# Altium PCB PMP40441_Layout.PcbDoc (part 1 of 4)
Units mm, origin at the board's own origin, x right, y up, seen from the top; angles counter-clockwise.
Board outline 66.04 x 61.04 mm, 4 copper layers (Top Layer, Layer 2, Layer 3, Bottom Layer), stack 2.028 mm thick; 208 components, 122 nets, 788 pads, 545 vias.
Unrouted connection lines stored in the file: 24.
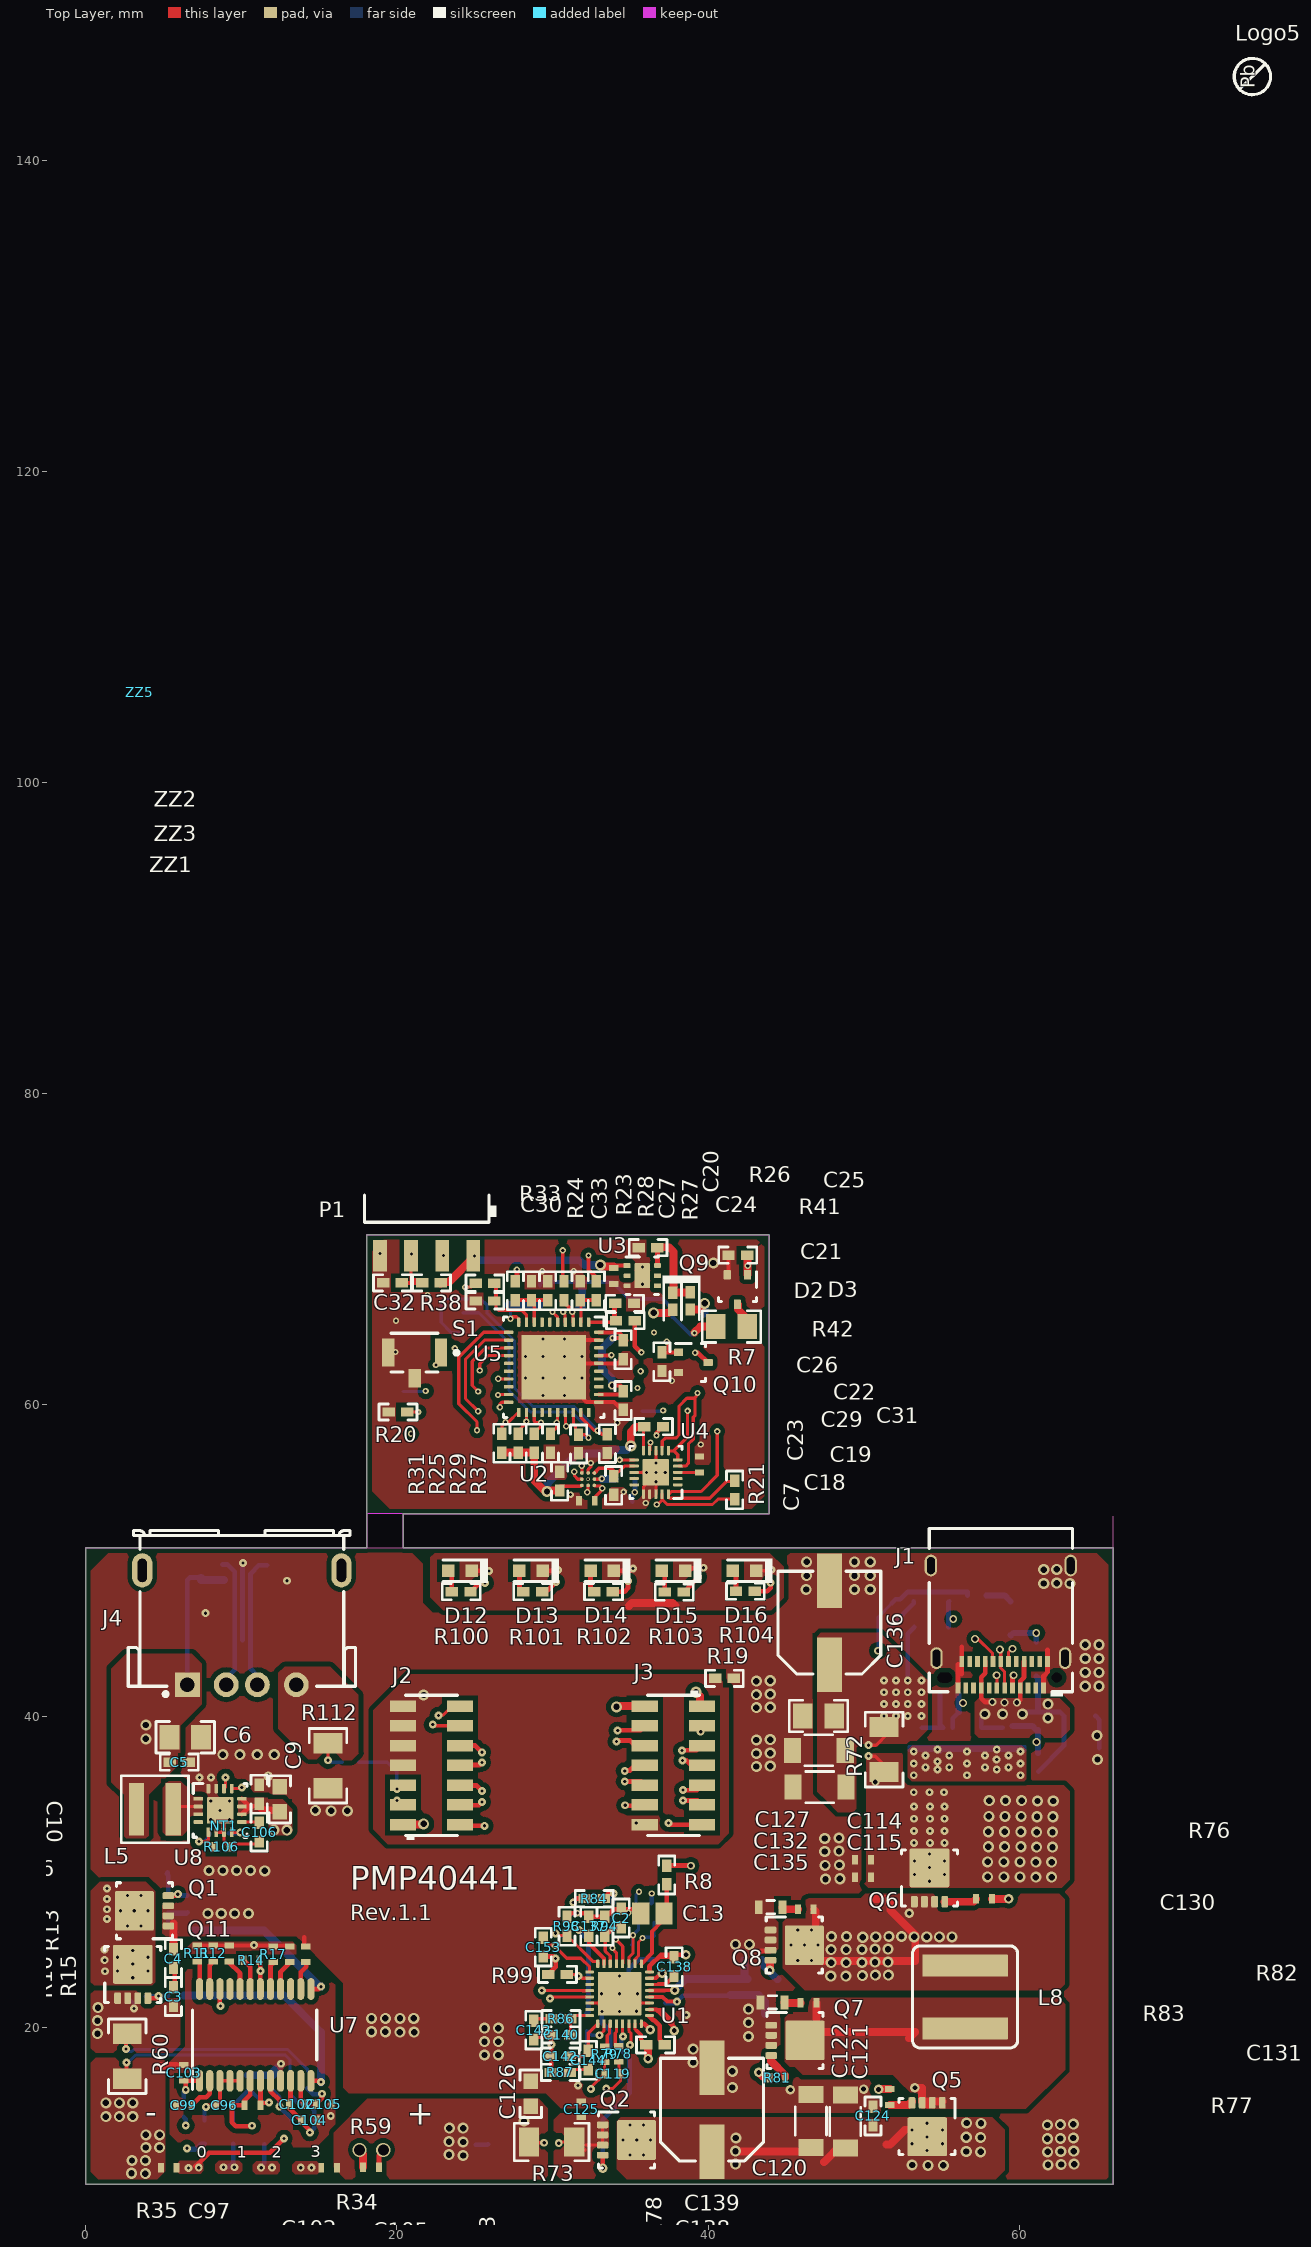
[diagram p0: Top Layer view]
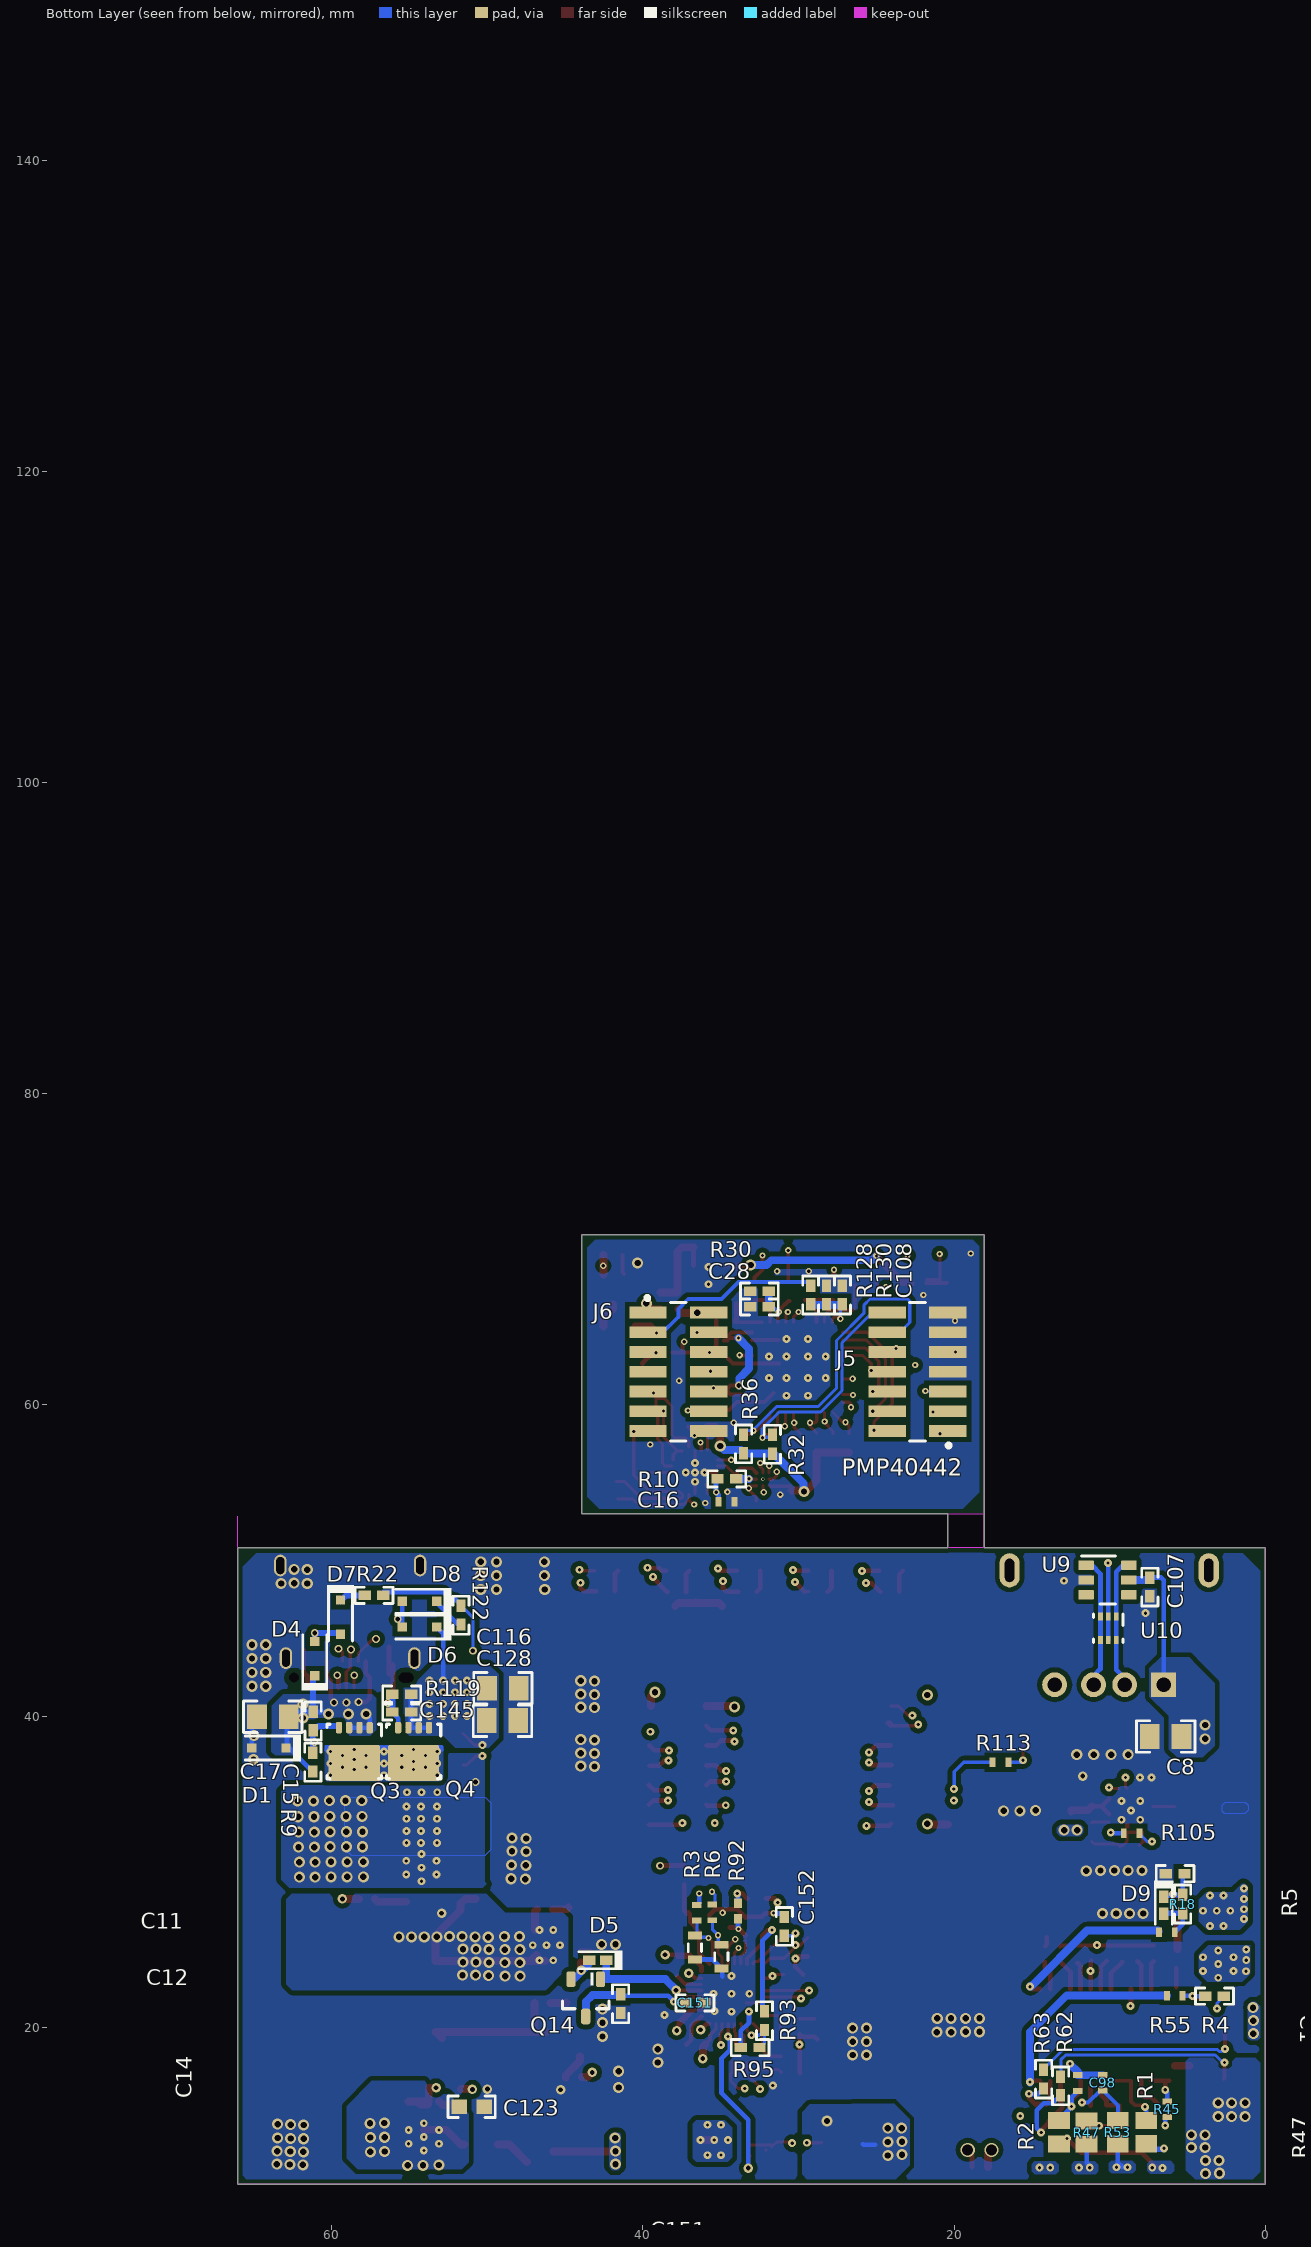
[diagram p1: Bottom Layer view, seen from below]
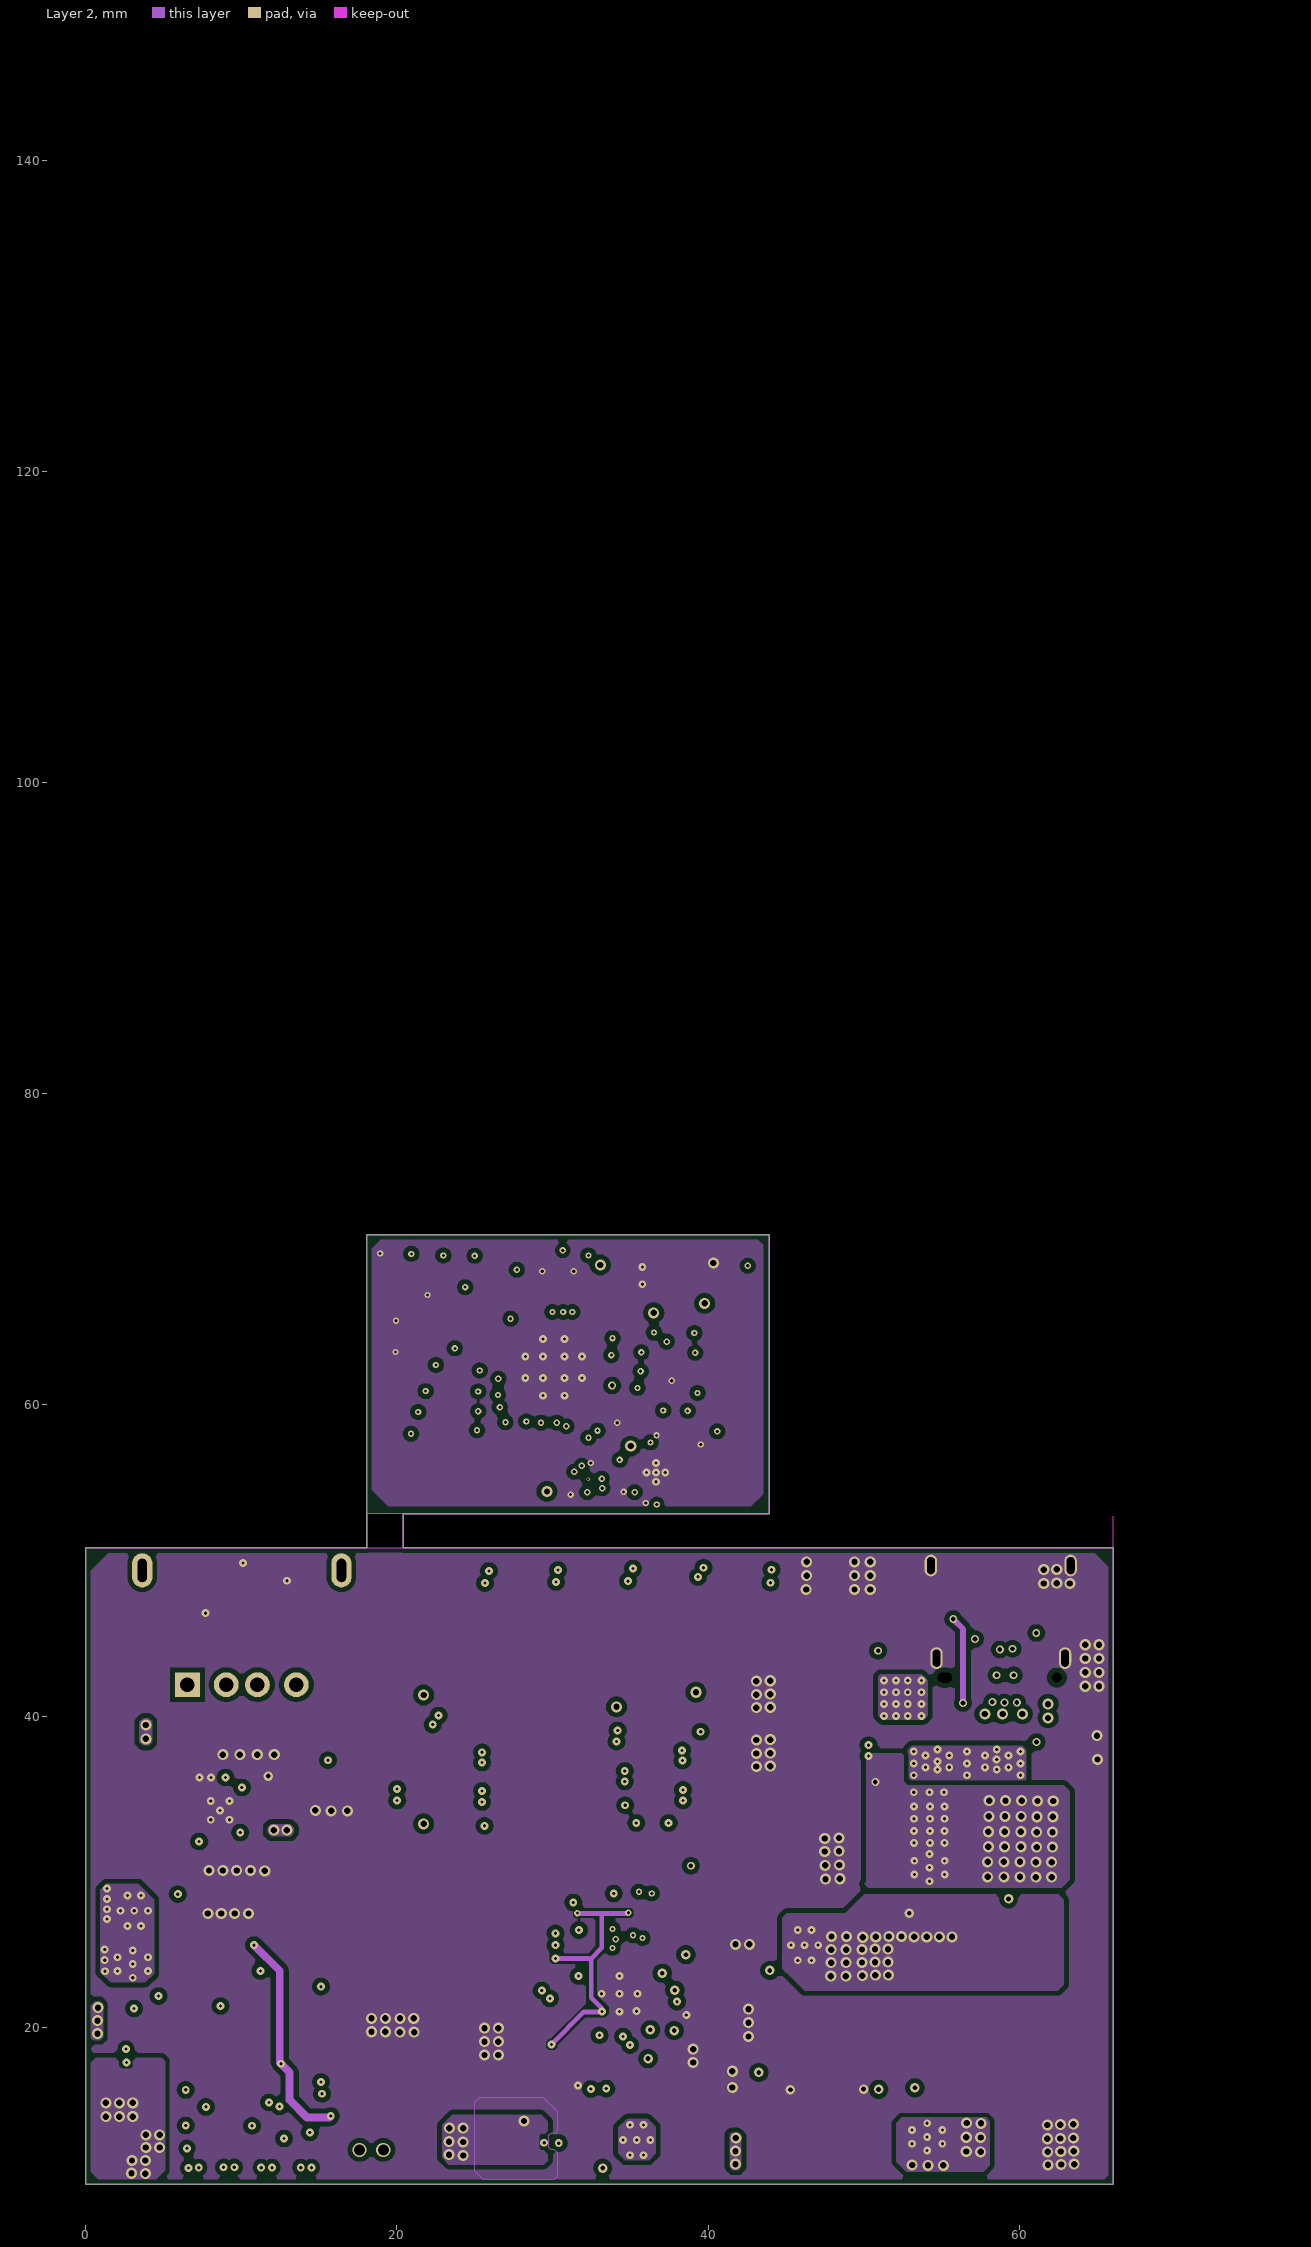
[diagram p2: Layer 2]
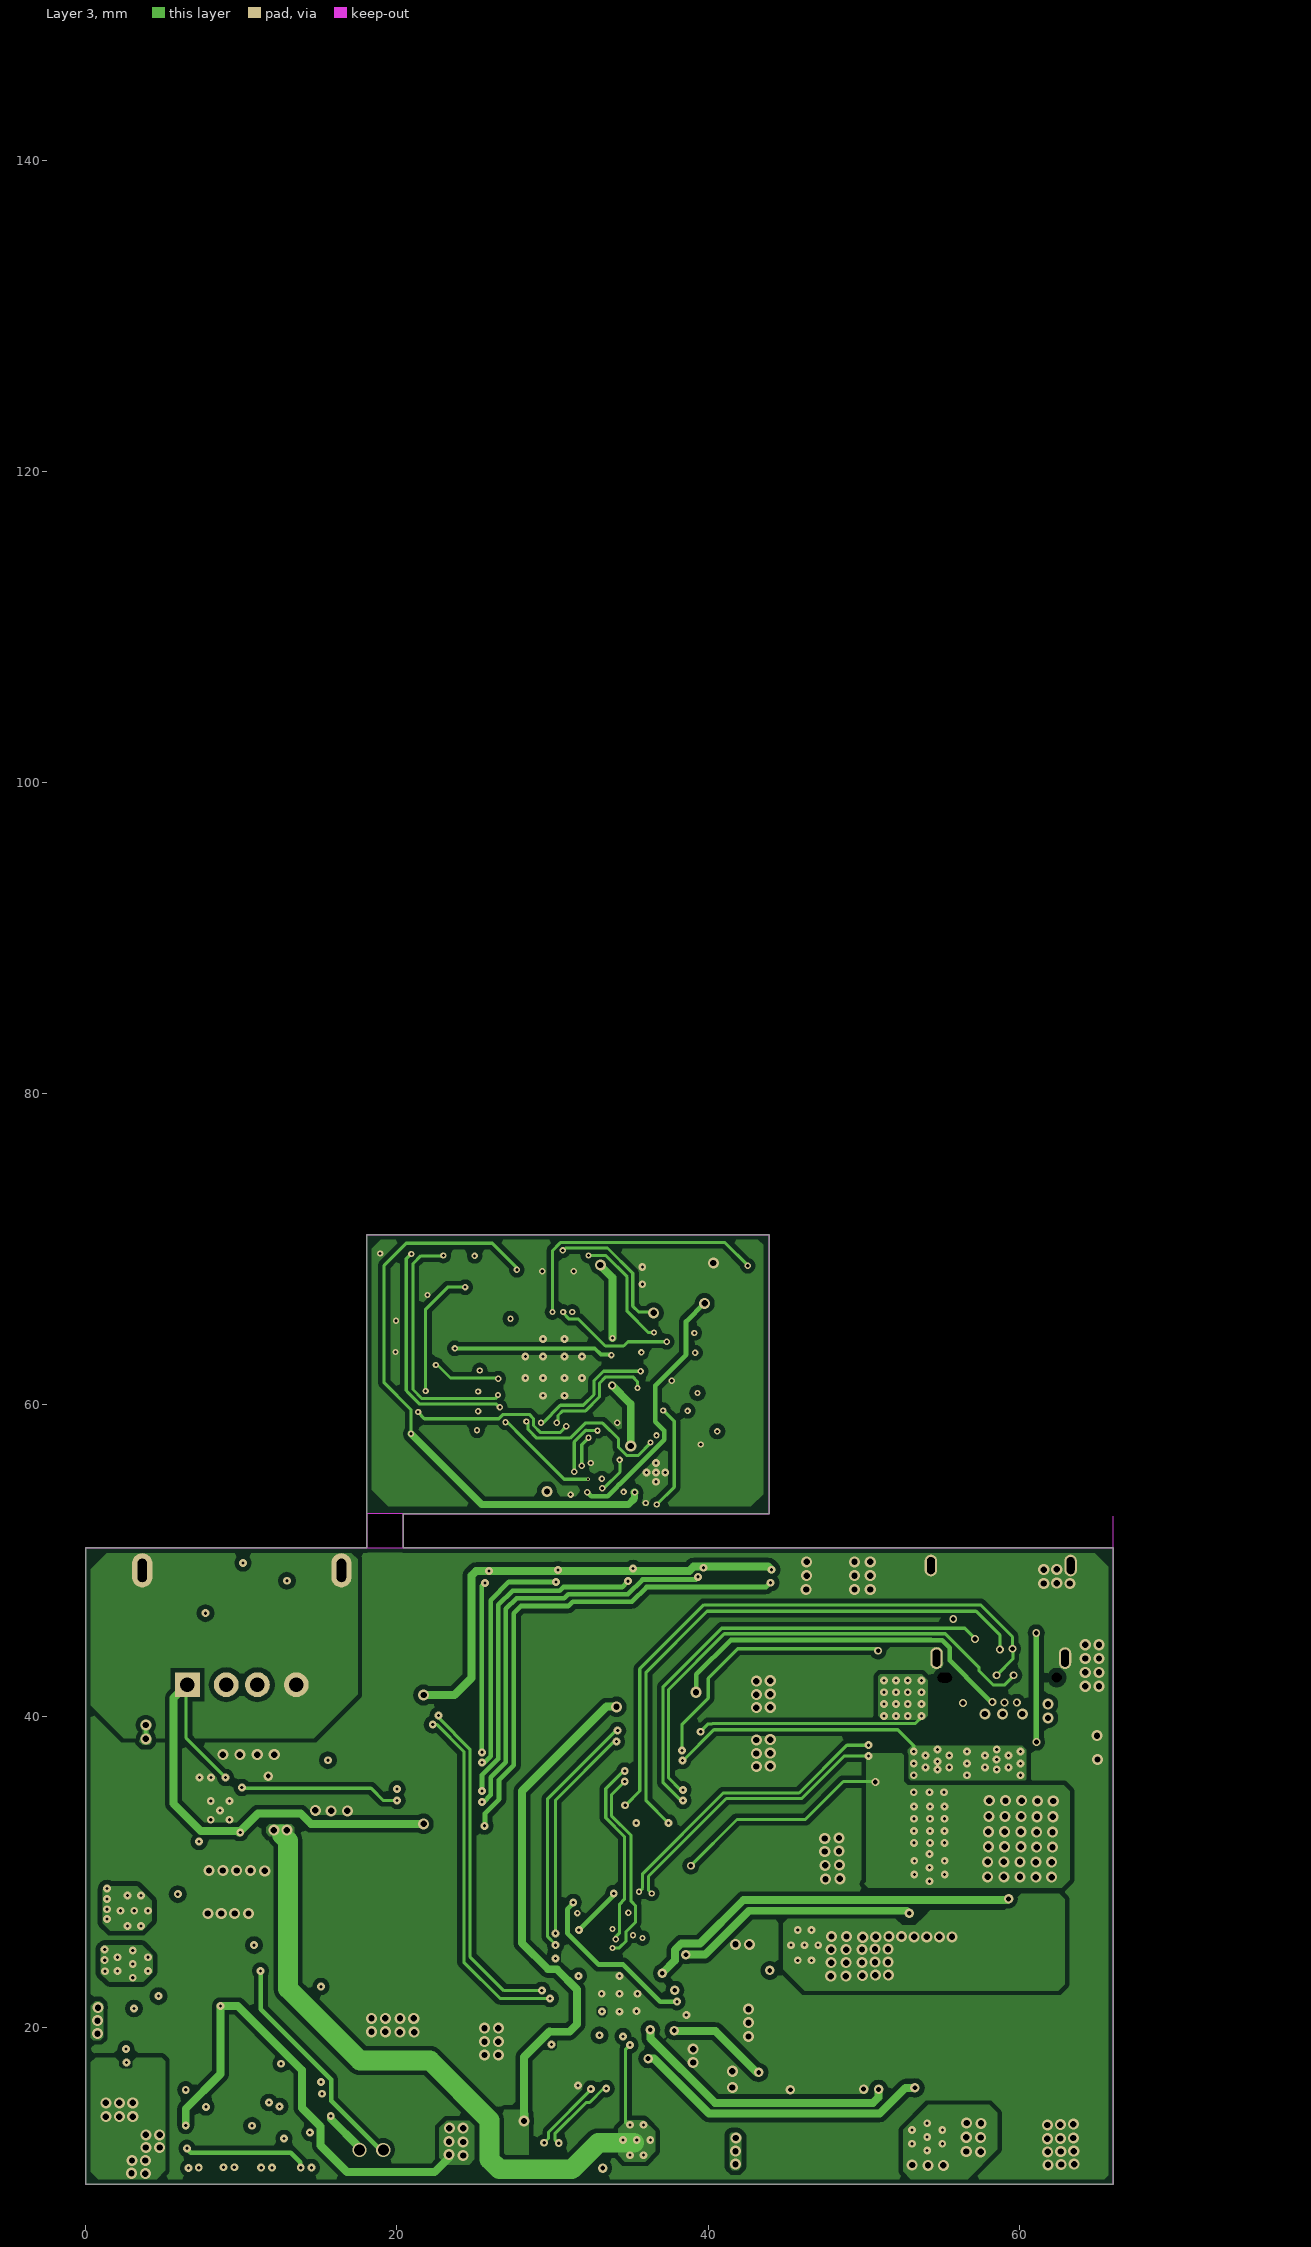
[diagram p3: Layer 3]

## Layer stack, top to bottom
Top Solder: solder mask 0.0102, Solder Resist, Dk 3.5
Top Layer: signal copper 0.0356
Dielectric1: core 1.5037, FR-4, Dk 4.8
Layer 2: signal copper 0.036
Dielectric 3: prepreg 0.127, Dk 4.2
Layer 3: signal copper 0.036
Dielectric 2: core 0.254, Dk 4.2
Bottom Layer: signal copper 0.0356
Bottom Solder: solder mask 0.0102, Solder Resist, Dk 3.5

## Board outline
0,9.906 0,50.8 18.059,50.8 18.059,70.942 43.942,70.942 43.942,53.01 20.396,53.01 20.396,50.8 66.04,50.8 66.04,9.906
cut-out: 18.059,53.01 18.059,50.8 20.396,50.8 20.396,53.01

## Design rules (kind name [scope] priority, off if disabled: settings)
AcuteAngle [All] p1: minimum=4.50000000000000E+0001 checktracksonly=FALSE
AssemblyTestPointUsage [All] p1: valid=2
Clearance Clearance_In [InNet('VBUS') vs InNet('PGND')] p1: gap=0.305 ignorepadtopadclearanceinfootprint=FALSE except(0: Arc-Hole Track-Hole SMDPad-Hole THPad-Hole Via-Hole Fill-Hole Poly-Hole Region-Hole Text-Hole)
Clearance Clearance_Keepouts [((IsTrack Or IsArc) And Not InPoly) And IsFree and IsKeepOut vs ((IsTrack Or IsArc) And Not InPoly) And IsFree and IsKeepOut] p2: gap=0.305 ignorepadtopadclearanceinfootprint=FALSE except(0: Arc-Hole Track-Hole SMDPad-Hole THPad-Hole Via-Hole Fill-Hole Poly-Hole Region-Hole Text-Hole)
Clearance Clearance_BoardEdge_MountingHoles [OnCopper and InComponentClass('Mounting Holes') vs IsKeepOut] p3: gap=0.305 ignorepadtopadclearanceinfootprint=FALSE except(0: Arc-Hole Track-Hole SMDPad-Hole THPad-Hole Via-Hole Fill-Hole Poly-Hole Region-Hole Text-Hole)
Clearance Clearance_BoardEdge_Poly [OnCopper and InPoly vs IsKeepOut] p4: gap=0.305 ignorepadtopadclearanceinfootprint=FALSE except(0: Arc-Hole Track-Hole SMDPad-Hole THPad-Hole Via-Hole Fill-Hole Poly-Hole Region-Hole Text-Hole)
Clearance Clearance_BoardEdge [OnCopper and Not InComponentClass('Logo') and not InComponentClass('FiducialMark') and not InRegion(1000,500,4000,800) and Not IsKeepout vs IsKeepOut] p5: gap=0.305 ignorepadtopadclearanceinfootprint=FALSE except(0: Arc-Hole Track-Hole SMDPad-Hole THPad-Hole Via-Hole Fill-Hole Poly-Hole Region-Hole Text-Hole)
Clearance Clearance_Poly [InPolygon] p6: gap=0.305 ignorepadtopadclearanceinfootprint=FALSE except(0: Arc-Hole Track-Hole SMDPad-Hole THPad-Hole Via-Hole Fill-Hole Poly-Hole Region-Hole Text-Hole)
Clearance [All] p7: gap=0.152 ignorepadtopadclearanceinfootprint=FALSE except(0: Arc-Hole Track-Hole SMDPad-Hole THPad-Hole Via-Hole Fill-Hole Poly-Hole Region-Hole Text-Hole)
ComponentClearance ComponentClearance_NT [InComponent('NT1')] p1: gap=0 collisioncheckmode=3 verticalgap=0 showdistances=FALSE
ComponentClearance ComponentClearance_MountingHoles_FiducialMarks [InComponentClass('Mounting Holes') vs InComponentClass('FiducialMark')] p2: gap=0.305 collisioncheckmode=3 verticalgap=0.254 showdistances=FALSE
ComponentClearance ComponentClearance_Shunt [InComponentClass('Header') vs InComponentClass('Shunt')] p3: gap=0 collisioncheckmode=3 verticalgap=0 showdistances=FALSE
ComponentClearance ComponentClearance_Logo [InComponentClass('Logo')] p4: gap=0.305 collisioncheckmode=3 verticalgap=0.254 showdistances=FALSE
ComponentClearance ComponentClearance_ScrewToNut [(HasFootprint('NY PMS 440 0025 PH')) vs (HasFootprint('Keystone_1902C'))] p5: gap=0.127 collisioncheckmode=3 verticalgap=0.254 showdistances=FALSE
ComponentClearance ComponentClearance_MountingHoles [InComponentClass('Mounting Holes')] p6: gap=0.305 collisioncheckmode=3 verticalgap=2540 showdistances=FALSE
ComponentClearance ComponentClearance_SmallPassives [HasFootprint('0201*') or HasFootprint('0402*') or HasFootprint('0508') or HasFootprint('0603*') or HasFootprint('0612') or HasFootprint('0805*') or HasFootprint('0815*') or HasFootprint('0830*') or HasFootprint('1206*') or HasFootprint('1210*') or HasFootprint('1808*') or HasFootprint('1812*') or HasFootprint('1825*') or HasFootprint('2010*') or HasFootprint('2220*') or HasFootprint('2225*') or HasFootprint('2512*') or HasFootprint('2728*') or HasFootprint('3518*') vs HasFootprint('0201*') or HasFootprint('0402*') or HasFootprint('0508') or HasFootprint('0603*') or HasFootprint('0612') or HasFootprint('0805*') or HasFootprint('0815*') or HasFootprint('0830*') or HasFootprint('1206*') or HasFootprint('1210*') or HasFootprint('1808*') or HasFootprint('1812*') or HasFootprint('1825*') or HasFootprint('2010*') or HasFootprint('2220*') or HasFootprint('2225*') or HasFootprint('2512*') or HasFootprint('2728*') or HasFootprint('3518*')] p7: gap=0.305 collisioncheckmode=3 verticalgap=0.254 showdistances=FALSE
ComponentClearance ComponentClearance_THtoSMT [IsThruComponent vs IsSMTComponent] p8: gap=2.54 collisioncheckmode=3 verticalgap=0.762 showdistances=FALSE
ComponentClearance ComponentClearance_THtoTH [IsThruComponent vs IsThruComponent] p9: gap=3 collisioncheckmode=3 verticalgap=0.762 showdistances=FALSE
ComponentClearance [All] p10: gap=0.305 collisioncheckmode=3 verticalgap=0.254 showdistances=FALSE
DiffPairsRouting [All] p1: maxlimit=2.54 minlimit=0.152 mostfreqgap=0.254 toplayer_minwidth=0.381 toplayer_maxwidth=0.381 toplayer_prefwidth=0.381 midlayer1_minwidth=0.381 midlayer1_maxwidth=0.381 midlayer1_prefwidth=0.381 midlayer2_minwidth=0.381 midlayer2_maxwidth=0.381 midlayer2_prefwidth=0.381 bottomlayer_minwidth=0.381 bottomlayer_maxwidth=0.381 bottomlayer_prefwidth=0.381 maxuncoupledlength=25.4
FabricationTestPointUsage TestPointUsage [All] p1: valid=2 allowmultiple=FALSE
FabricationTestpoint Testpoint [All] p1: side=3 testpointundercomponent=TRUE minsize=1.016 maxsize=2.54 preferedsize=1.524 minholesize=0 maxholesize=1.016 preferedholesize=0.813 testpointgrid=0.025 allowsidetop=TRUE allowsidebottom=TRUE usegrid=TRUE gridtolerance=0
FanoutControl Fanout_LCC [IsLCC] p1: bgadir=Out bgaviamode=Centered fanoutstyle=Auto fanoutdirection=Alternating viagrid=0.025 // Fanout_LCC (Default Rule)
FanoutControl Fanout_BGA [IsBGA] p2: bgadir=Out bgaviamode=Centered fanoutstyle=Auto fanoutdirection=Alternating viagrid=0.025 // Fanout_BGA (Default Rule)
FanoutControl Fanout_Default [All] p4: bgadir=Out bgaviamode=Centered fanoutstyle=Auto fanoutdirection=Alternating viagrid=0.025 // Fanout_Default (Default Rule)
FanoutControl Fanout_Small [(CompPinCount < 5)] p5: bgadir=Out bgaviamode=Centered fanoutstyle=Auto fanoutdirection=OutThenIn viagrid=0.025 // Fanout_Small (Default Rule)
HoleSize [All] p1: absolutevalues=TRUE maxlimit=6.375 minlimit=0.152 maxpercent=80.000 minpercent=20.000
HoleToHoleClearance [All] p1: gap=0.203 allowstackedmicrovias=TRUE
MinimumAnnularRing MinimumAnnularRing_ThermalPadVias [IsVia and InAnyComponent] p1: minimumring=0.15
MinimumAnnularRing [All] p2: minimumring=0.1
MinimumSolderMaskSliver MinimumSolderMaskSliver_Logo [InComponentClass('Logo') vs InComponentClass('Logo')] p1: minsoldermaskwidth=0.018
MinimumSolderMaskSliver [All] p2: minsoldermaskwidth=0.018
PlaneClearance [All] p1: clearance=0.305
PlaneConnect [All] p1: planeconnectstyle=Direct reliefexpansion=0.254 reliefentries=4 reliefconductorwidth=0.254 reliefairgap=0.254
PolygonConnect [All] p1: connectstyle=Direct reliefconductorwidth=0.254 reliefentries=4 polygonreliefangle="90 Angle" airgapwidth=0.254
RoutingVias ThermalPadVias [IsVia and InAnyComponent] p1: holewidth=0.2 width=0.5 viastyle="Through Hole" minholewidth=0.152 minwidth=0.457 maxholewidth=0.33 maxwidth=0.6
RoutingVias [All] p2: holewidth=0.406 width=0.864 viastyle="Through Hole" minholewidth=0.152 minwidth=0.352 maxholewidth=1.016 maxwidth=1.651
SilkToBoardRegionClearance [Not ((IsComment or IsDesignator) And (Hide <> 'False')) and not InRegion(1000,500,4000,800)] p1:
SilkToSilkClearance SilkToSilkClearance_Pb-FreeLogo [(HasFootprint('Pb-Free_Overlay_Medium') OR HasFootprint('Pb-Free_Overlay_Small')) vs (HasFootprint('Pb-Free_Overlay_Medium') OR HasFootprint('Pb-Free_Overlay_Small'))] p1: silktosilkclearance=0
SilkToSilkClearance [All] p2: silktosilkclearance=0
SilkToSolderMaskClearance SilkToComonentPadClearance [IsPad and InAnycomponent] p1: minsilkscreentomaskgap=0.076 clearancetoexposedcopper=TRUE
SilkToSolderMaskClearance "Silk to Solder Mask Opening" [All] p2: minsilkscreentomaskgap=0 clearancetoexposedcopper=FALSE
SolderMaskExpansion [All] p1: expansion=0.05
Width [All] p1: maxlimit=2.54 minlimit=0.152 preferedwidth=0.254 checkconnectedcopper=TRUE
13 further rules are at their usual default settings.

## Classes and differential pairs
component class AssemblyNote: ZZ1 ZZ2 ZZ3 ZZ4 ZZ5 ZZ6 ZZ7 ZZ8
component class "PMP40441_Main -20180625": C1 C2 C3 C4 C5 C6 C8 C9 C10 C11 C12 C13 C14 C15 C17 C96 C97 C98 C99 C102 C103 C104 C105 C106 C107 C114 C115 C116 C119 C120 C121 C122 C123 C124 C125 C126 C127 C128 C130 C131 C132 C135 C136 C137 C138 C139 C140 C142 C143 C144 C145 C151 C152 C153 D1 D4 D5 D6 D7 D8 D9 D12 D13 D14 D15 D16 J1 J2 J3 J4 L5 L8 NT1 Q1 Q2 Q3 Q4 Q5 Q6 Q7 Q8 Q11 Q14 R1 R2 R3 R4 R5 R6 R8 R9 R11 R12 R13 R14 R15 R16 R17 R18 R19 R22 R34 R35 R45 R47 R53 R55 R57 R59 R60 R62 R63 R72 R73 R76 R77 R78 R79 R81 R82 R83 R84 R86 R87 R92 R93 R94 R95 R98 R99 R100 R101 R102 R103 R104 R105 R106 R112 R113 R119 R122 U1 U7 U8 U9 U10 ZZ1 ZZ2 ZZ3 ZZ4
component class Header: J5 J6 P1
component class PMP40442_Main: C7 C16 C18 C19 C20 C21 C22 C23 C24 C25 C26 C27 C28 C29 C30 C31 C32 C33 C108 D2 D3 J5 J6 Logo5 P1 Q9 Q10 R7 R10 R20 R21 R23 R24 R25 R26 R27 R28 R29 R30 R31 R32 R33 R36 R37 R38 R41 R42 R128 R130 S1 U2 U3 U4 U5 ZZ5 ZZ6 ZZ7 ZZ8

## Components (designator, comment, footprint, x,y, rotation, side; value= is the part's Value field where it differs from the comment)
C1 "C1005X5R1C105K050BC" 0402S 12.04,16.408 r270 bottom value=1uF
C2 "GRM1555C1H101JA01D" 0402 34.417,27.017 r90 top value=100pF
C3 "GRM155R61C104KA88D" 0402 5.639,21.971 r270 top value=0.1uF
C4 "GRM155R61C104KA88D" 0402 5.639,24.409 r270 top value=0.1uF
C5 "GRM155R61C104KA88D" 0402 6.01,37.033 r180 top value=0.1uF
C6 "JMK212BJ476MG-T" 0805_HV 6.401,38.633 r0 top value=47uF
C7 "885012105012" 0402 30.455,55.093 r270 top value=1uF
C8 "JMK212BJ476MG-T" 0805_HV 6.401,38.684 r0 bottom value=47uF
C9 "GRM188R61E106MA73D" 0603 12.471,34.646 r90 top value=10uF
C10 "GRM155R61E104KA87D" 0402 11.151,34.976 r90 top value=0.1uF
C11 "GRM188R71H333KA61D" 0603S 36.652,25.121 r270 bottom value=0.033uF
C12 "GRM188R71H333KA61D" 0603S 34.95,24.536 r90 bottom value=0.033uF
C13 "GRM21BR71H474KA88L" 0805L 36.419,27.301 r0 top value=0.47uF
C14 "GRM155R61C473KA01D" 0402 41.427,21.514 r90 bottom value=0.047uF
C15 "C0402C102J3RACTU" 0402 61.189,39.675 r90 bottom value=1000pF
C16 "CL05A106MP5NUNC" 0402S 34.62,53.772 r180 bottom value=10uF
C17 "GRM21BR6YA106KE43L" 0805_HV 63.779,39.954 r0 bottom value=10uF
C18 "GRM1555C1H221JA01D" 0402S 32.207,53.823 r0 top value=220pF
C19 "GRM1555C1H221JA01D" 0402 33.934,54.823 r90 top value=220pF
C20 "C1005X5R0J475M050BC" 0402S 33.934,68.285 r270 top value=4.7uF
C21 "GRM155R6YA105KE11D" 0402 36.144,70.104 r0 top value=1uF
C22 "885012105012" 0402 36.5,58.598 r180 top value=1uF
C23 "GRM155R61H104ME14D" 0402S 39.446,56.159 r90 top value=0.1uF
C24 "GRM155R61C103KA01D" 0402 34.636,66.523 r0 top value=0.01uF
C25 "C1005X5R1A104K050BA" 0402 34.544,63.541 r90 top value=0.1uF
C26 "C1005X5R1A104K050BA" 0402 34.544,60.274 r90 top value=0.1uF
C27 "GRM155R61C103KA01D" 0402 31.775,67.335 r90 top value=0.01uF
C28 "GRM155R61C103KA01D" 0402 32.512,66.294 r180 bottom value=0.01uF
C29 "GRM1555C1H470FA01D" 0402 31.674,57.48 r270 top value=47pF
C30 "GRM155R61C104KA88D" 0402 25.654,66.675 r180 top value=0.1uF
C31 "GRM1555C1H470FA01D" 0402 33.528,57.506 r270 top value=47pF
C32 "C0402C112J5GAC7867" 0402 19.71,67.843 r180 top value=1100pF
C33 "GRM155R61C103KA01D" 0402 28.651,67.335 r270 top value=0.01uF
C96 "C1005X5R1C105K050BC" 0402S 8.89,14.986 r0 top value=1uF
C97 "C1005X5R1C105K050BC" 0402S 10.719,14.986 r0 top value=1uF
C98 "C1005X5R1C105K050BC" 0402S 10.439,16.434 r90 bottom value=1uF
C99 "C1005X5R1C105K050BC" 0402S 6.299,14.986 r180 top value=1uF
C102 "GRM155R61C104KA88D" 0402S 13.564,15.037 r0 top value=0.1uF
C103 "C1005X5R1E105K050BC" 0402S 6.299,17.069 r90 top value=1uF
C104 "GRM155R61C104KA88D" 0402S 14.351,14.021 r180 top value=0.1uF
C105 "GRM155R61C104KA88D" 0402S 15.291,15.037 r0 top value=0.1uF
C106 "GRM155R71H332KA01D" 0402 11.151,32.537 r90 top value=3300pF
C107 "GRM155R61C104KA88D" 0402 7.417,48.285 r270 bottom value=0.1uF
C108 "GRM155R61C103KA01D" 0402 27.178,67.056 r270 bottom value=0.01uF
C114 "GRM155R71H103KA88D" 0402S 49.955,30.759 r180 top value=0.01uF
C115 "GRM155R61H102KA01D" 0402S 49.956,29.645 r180 top value=1000pF
C116 "GRM21BR6YA106KE43L" 0805_HV 48.997,41.783 r180 bottom value=10uF
C119 "GRM155R61E104KA87D" 0402S 33.858,17.018 r0 top value=0.1uF
C120 "EEHZA1E560P" SM_RADIAL_6.3AMM 40.259,14.707 r90 top value=56uF
C121 "C3216X5R1E476M160AC" 1206_190 48.819,13.945 r90 top value=47uF
C122 "C3216X5R1E476M160AC" 1206_190 46.609,13.97 r90 top value=47uF
C123 "GRM188R61E106MA73D" 0603 51.003,14.884 r180 bottom value=10uF
C124 "GRM155R61E104KA87D" 0402 50.597,14.3 r90 top value=0.1uF
C125 "GRM155R61E105KA12D" 0402S 31.852,14.732 r90 top value=1uF
C126 "GRM188R61E106MA73D" 0603 28.6,15.723 r90 top value=10uF
C127 "GRM21BR6YA106KE43L" 0805_HV 47.092,40.005 r0 top value=10uF
C128 "GRM21BR6YA106KE43L" 0805_HV 49.022,39.7 r0 bottom value=10uF
C130 "GRM1555C1H331JA01D" 0402S 46.279,27.584 r180 top value=330pF
C131 "GRM1555C1H331JA01D" 0402S 46.449,21.567 r180 top value=330pF
C132 "C3216X5R1V226M160AC" 1206_190 47.117,37.795 r0 top value=22uF
C135 "C3216X5R1V226M160AC" 1206_190 47.168,35.433 r0 top value=22uF
C136 "EEHZA1E560P" SM_RADIAL_6.3AMM 47.803,45.999 r90 top value=56uF
C137 "C1005X5R1C105K050BC" 0402 32.336,26.492 r90 top value=1uF
C138 "GRM155R61C473KA01D" 0402 37.813,23.892 r270 top value=0.047uF
C139 "GRM155R61C473KA01D" 0402 36.619,18.873 r180 top value=0.047uF
C140 "GRM1555C1H330JA01D" 0402 30.548,19.507 r180 top value=33pF
C142 "GRM1555C1H150JA01D" 0402 30.498,18.136 r0 top value=15pF
C143 "GRM155R71H182KA01D" 0402 28.796,19.812 r270 top value=1800pF
C144 "GRM1555C1H681JA01D" 0402 32.301,17.882 r90 top value=680pF
C145 "C0402C102J3RACTU" 0402 55.499,40.259 r0 bottom value=1000pF
C151 "C1005X5R1C225K050BC" 0402 36.652,21.565 r0 bottom value=2.2uF
C152 "GRM1555C1H101JA01D" 0402 30.912,26.483 r90 bottom value=100pF
C153 "GRM1555C1H101JA01D" 0402 29.405,25.146 r270 top value=100pF
D1 "CDSOD323-T24S" SOD-323 64.033,37.948 r0 bottom value=24V
D2 "BAS 52-02V H6327" SOD-523 38.862,66.675 r270 top value=45V
D3 "BAS 52-02V H6327" SOD-523 37.719,66.65 r270 top value=45V
D4 "BZX384-C15,115" SOD-323 61.087,43.688 r90 bottom value=15V
D5 "BAS 52-02V H6327" SOD-523 42.901,24.308 r0 bottom value=45V
D6 "BZX384-C15,115" SOD-323 54.356,45.72 r0 bottom value=15V
D7 "1N4148WX-TP" SOD-323 59.436,46.355 r270 bottom value=75V
D8 "1N4148WX-TP" SOD-323 54.356,47.371 r0 bottom value=75V
D9 "RB521S30T1G" SOD-523 6.528,27.838 r270 bottom value=30V
D12 "LTST-C190GKT" LED_LTST-C190 24.054,49.34 r0 top value=Green
D13 "LTST-C190GKT" LED_LTST-C190 28.626,49.34 r0 top value=Green
D14 "LTST-C190GKT" LED_LTST-C190 33.198,49.34 r0 top value=Green
D15 "LTST-C190GKT" LED_LTST-C190 37.77,49.34 r0 top value=Green
D16 "LTST-C190KFKT" LED_LTST-C190 42.342,49.34 r0 top value=Orange
J1 "12401610E4#2A" Amphenol_12401610E4_2A 58.809,42.47 r180 top locked
J2 "FLE-107-01-G-DV" Samtec_FLE-107-01-x-DV 22.225,36.83 r90 top locked
J3 "FLE-107-01-G-DV" Samtec_FLE-107-01-x-DV 37.77,36.83 r270 top locked
J4 "614 104 150 121" WURTH_614104150121 10.033,42.012 r180 top
J5 "20021121-00014T4LF" FCI_20021121-00014x4 22.352,62.128 r0 bottom locked
J6 "20021121-00014T4LF" FCI_20021121-00014x4 37.719,62.128 r180 bottom locked
L5 "XFL4020-222MEB" XFL4020 4.445,34.011 r0 top value=2.2uH
L8 "XEL6060-222MEB" XEL6060 56.515,21.946 r270 top value=2.2uH
Logo5 "Pb-Free Symbol" Pb-Free_Overlay_Small 74.981,145.364 r90 top
NT1 "Net-Tie" Net-Tie_10mil 8.865,32.944 r90 top net-tie
P1 "M22-5330405" Harwin_M22-5330405 21.911,69.571 r180 top
Q1 "CSD16323Q3" DQG0008A 3.785,27.483 r180 top value=25V
Q2 "CSD25404Q3" DQG0008A 34.747,12.751 r0 top value=-20V
Q3 "SI7101DN-T1-GE3" PowerPAK_1212-8 58.547,37.719 r270 bottom value=-30V
Q4 "SI7101DN-T1-GE3" PowerPAK_1212-8 54.737,37.719 r270 bottom value=-30V
Q5 "CSD17308Q3" DQG0008A 54.077,13.614 r270 top value=30V
Q6 "CSD17308Q3" DQG0008A 54.229,29.591 r90 top value=30V
Q7 "CSD17308Q3" CSD17308Q3 45.585,19.154 r0 top value=30V
Q8 "CSD17308Q3" DQG0008A 45.535,25.275 r0 top value=30V
Q9 "BSS138W" SOT-323 41.885,67.412 r270 top value=50V
Q10 "BSS138W" SOT-323 39.05,62.723 r0 top value=50V
Q11 "CSD16323Q3" DQG0008A 3.023,23.393 r90 top value=25V
Q14 "NSS12201LT1G" SOT-23 43.673,21.889 r270 bottom value="12 V"
R1 "CRCW080533R0JNEA" 0805L 7.645,13.259 r270 bottom value=33
R2 "CRCW080533R0JNEA" 0805L 13.259,13.247 r270 bottom value=33
R3 "CRCW04024R99FKED" 0402S 36.525,27.356 r270 bottom value=4.99
R4 "CRCW040210M0JNED" 0402 3.261,21.996 r180 bottom value=10Meg
R5 "CRCW04023M00JNED" 0402 5.791,29.87 r0 bottom value=3.0Meg
R6 "CRCW04024R99FKED" 0402S 35.535,27.381 r270 bottom value=4.99
R7 "CRCW08051K00FKEA" 0805_HV 41.504,65.024 r180 top value=1.00k
R8 "CRCW04021R00JNED" 0402 37.342,29.789 r270 top value=1.0
R9 "RC0402FR-071ML" 0402 61.214,37.033 r90 bottom value=1.00Meg
R10 "CRCW04020000Z0ED" 0402 34.604,55.245 r0 bottom value=0
R11 "CRCW04020000Z0ED" 0402S 7.163,24.74 r90 top value=0
R12 "CRCW04020000Z0ED" 0402S 8.204,24.74 r90 top value=0
R13 "CRCW04020000Z0ED" 0402S 9.22,24.74 r90 top value=0
R14 "CRCW040210K0FKED" 0402S 10.643,24.308 r180 top value=10.0k
R15 "CRCW0402470KJNED" 0402S 14.148,24.689 r90 top value=470k
R16 "CRCW04020000Z0ED" 0402S 13.106,24.689 r90 top value=0
R17 "CRCW0402196KFKED" 0402S 12.065,24.689 r90 top value=196k
R18 "CRCW04021M00JNED" 0402 5.309,27.915 r90 bottom value=1.0Meg
R19 "CRCW04020000Z0ED" 0402 41.046,42.418 r180 top value=0
R20 "CRCW0402100KFKED" 0402 20.076,59.538 r180 top value=100k
R21 "CRCW0402200RFKED" 0402 41.707,54.534 r90 top value=200
R22 "RG1005P-104-B-T5" 0402 57.277,47.752 r180 bottom value=100k
R23 "CRCW04023M01FKED" 0402 29.693,67.335 r90 top value=3.01Meg
R24 "CRCW04022M00FKED" 0402 27.61,67.335 r270 top value=2.00Meg
R25 "CRCW0402100KJNED" 0402 27.788,57.531 r270 top value=100k
R26 "RC0402FR-07100RL" 0402 34.681,65.405 r180 top value=100
R27 "RC0402FR-07100RL" 0402 32.817,67.335 r270 top value=100
R28 "CRCW04023M01FKED" 0402 30.734,67.335 r90 top value=3.01Meg
R29 "CRCW04021M00FKED" 0402 28.829,57.531 r90 top value=1.00Meg
R30 "RC0402FR-07330KL" 0402 32.512,67.31 r180 bottom value=330k
R31 "CRCW0402200KFKED" 0402 26.746,57.531 r90 top value=200k
R32 "CRCW040210K0FKED" 0402 31.674,57.464 r90 bottom value=10.0k
R33 "CRCW0402220RJNED" 0402 25.654,67.818 r180 top value=220
R34 "CRCW04020000Z0ED" 0402S 15.646,10.973 r0 top value=0
R35 "CRCW04020000Z0ED" 0402S 5.334,10.973 r180 top value=0
R36 "CRCW040210K0FKED" 0402 33.528,57.49 r90 bottom value=10.0k
R37 "CRCW0402100KJNED" 0402 29.87,57.531 r90 top value=100k
R38 "CRCW040247K0JNED" 0402 22.225,67.843 r0 top value=47k
R41 "CRCW0402100KFKED" 0402 41.91,69.621 r0 top value=100k
R42 "CRCW0402100KFKED" 0402 37.033,62.773 r90 top value=100k
R45 "CRCW04021K00JNED" 0402S 6.299,14.732 r270 bottom value=1.0k
R47 "CRCW080533R0JNEA" 0805L 11.481,13.233 r270 bottom value=33
R53 "CRCW080533R0JNEA" 0805L 9.474,13.259 r270 bottom value=33
R55 "CRCW04025K10JNED" 0402S 5.817,22.022 r180 bottom value=5.1k
R57 "CRCW04025K10JNED" 0402S 6.325,26.111 r0 bottom value=5.1k
R59 "ERT-J0EG103HA" 0402S 18.339,10.998 r0 top value="10k ohm"
R60 "WSLP1206R0100FEA" 1206 2.667,18.136 r90 top value=0.01
R62 "CRCW0402100RFKED" 0402 13.157,16.231 r90 bottom value=100
R63 "CRCW0402100RFKED" 0402 14.249,16.662 r90 bottom value=100
R72 "WSLP1206R0100FEA" 1206 51.308,37.846 r270 top value=0.01
R73 "WSLP1206R0100FEA" 1206 29.947,12.624 r180 top value=0.01
R76 "CRCW04020000Z0ED" 0402S 57.734,28.245 r180 top value=0
R77 "CRCW04020000Z0ED" 0402S 51.689,15.519 r90 top value=0
R78 "CRCW040210R0JNED" 0402S 34.265,18.288 r270 top value=10
R79 "CRCW040210R0JNED" 0402S 33.35,18.263 r270 top value=10
R81 "CRCW04020000Z0ED" 0402S 44.45,16.764 r180 top value=0
R82 "CRCW060356R0JNEA" 0603S 44.018,27.711 r0 top value=56
R83 "CRCW060356R0JNEA" 0603S 44.138,21.592 r0 top value=56
R84 "CRCW040210R0JNED" 0402 32.682,28.27 r180 top value=10
R86 "CRCW040240K2FKED" 0402 30.548,20.549 r0 top value=40.2k
R87 "CRCW040210K0FKED" 0402 30.498,17.094 r180 top value=10.0k
R92 "CRCW0402383KFKED" 0402L 33.884,27.475 r270 bottom value=383k
R93 "CRCW040280K6FKED" 0402 32.182,20.422 r90 bottom value=80.6k
R94 "CRCW0402221KFKED" 0402 33.368,26.492 r90 top value=221k
R95 "CRCW0402100KFKED" 0402 33.106,18.694 r180 bottom value=100k
R98 "CRCW0402137KFKED" 0402 30.929,26.492 r90 top value=137k
R99 "CRCW040230K1FKED" 0402 30.32,23.394 r180 top value=30.1k
R100 "CRCW04023K30JNED" 0402 24.13,47.993 r0 top value=3.3k
R101 "CRCW04023K30JNED" 0402 28.727,47.993 r0 top value=3.3k
R102 "CRCW04023K30JNED" 0402 33.274,47.993 r0 top value=3.3k
R103 "CRCW04023K30JNED" 0402 37.821,47.968 r0 top value=3.3k
R104 "CRCW04023K30JNED" 0402 42.393,48.019 r0 top value=3.3k
R105 "CRCW0402665KFKED" 0402S 8.585,32.461 r0 bottom value=665k
R106 "CRCW0402130KFKED" 0402S 8.712,31.598 r180 top value=130k
R112 "ERJ-8CWFR050V" 1206 15.57,36.805 r90 top value=0.05
R113 "CRCW04020000Z0ED" 0402S 17.018,37.033 r180 bottom value=0
R119 "RC0402FR-071ML" 0402 55.499,41.402 r0 bottom value=1.00Meg
R122 "RG1005P-104-B-T5" 0402 51.689,46.482 r90 bottom value=100k
R128 "CRCW04023M01FKED" 0402 29.21,67.056 r90 bottom value=3.01Meg
R130 "RC0402FR-07330KL" 0402 28.194,67.056 r270 bottom value=330k
S1 "B3U-1100P" SW_B3U-1100P 21.133,63.348 r180 top
U1 "BQ25713RSNR" RSN0032B 34.308,22.149 r270 top
U2 "TUSB422IYFPR" YFP0009-C01 32.29,55.22 r180 top
U3 "TPS70933DRVR" DRV0006A 35.773,68.301 r0 top
U4 "TPD6S300RUK" RUK0020B 36.645,55.659 r180 top
U5 "MSP430FR5949IRHAR" RHA0040B 30.078,62.412 r270 top
U7 "BQ7791500PWR" PW0024A_N 10.897,19.507 r90 top
U8 "TLV62130RGTR" RGT0016C 8.636,33.934 r0 top
U9 "TPS2514ADBVR" DBV0006A_N 10.138,48.743 r180 bottom
U10 "TPD2E1B06DRLR" DRL0006A 10.084,45.644 r270 bottom
ZZ1 "This Assembly Note is for PCB labels only" AssemblyNoteLabel 4.42,92.862 r0 top
ZZ2 "This Assembly Note will show in the PcbDoc and associated outputs" AssemblyNote 4.699,97.259 r0 top
ZZ3 "This Assembly Note will show in the PcbDoc and associated outputs" AssemblyNote 4.699,95.01 r0 top
ZZ4 "This Assembly Note will show in the PcbDoc and associated outputs" AssemblyNote 86.995,36.932 r90 top
ZZ5 "This Assembly Note is for PCB labels only" AssemblyNoteLabel 3.48,105.791 r0 top
ZZ6 "This Assembly Note will show in the PcbDoc and associated outputs" AssemblyNote 104.775,140.259 r90 top
ZZ7 "This Assembly Note will show in the PcbDoc and associated outputs" AssemblyNote 91.592,140.259 r90 top
ZZ8 "This Assembly Note will show in the PcbDoc and associated outputs" AssemblyNote 87.097,140.259 r90 top

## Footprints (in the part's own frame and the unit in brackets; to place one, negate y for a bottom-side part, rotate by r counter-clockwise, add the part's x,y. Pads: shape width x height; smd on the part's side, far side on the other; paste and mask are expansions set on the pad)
0402 [mm] "0402 from SM-752 data"
  rect 0.8x0.6 smd: 1(-0.6,0) 2(0.6,0)
  silkscreen extent -1.22,-0.52 1.22,0.52, body extent -0.55,-0.3 0.55,0.3, height 0.6
0402L [mm] "0402 from SM-752 data"
  rect 0.6x0.5 smd: 1(-0.5,0) 2(0.5,0)
  body extent -0.55,-0.3 0.55,0.3, height 0.6
0402S [mil] "Based on C0402S footprint from PADS legacy"
  rect 15x24 smd: 1(-20,0) 2(20,0)
  body extent -22,-12 22,12, height 24
0603 [mm] "0603 from SM-752 data"
  rect 1x0.95 smd: 1(-0.8,0) 2(0.8,0)
  silkscreen extent -1.52,-0.69 1.52,0.69, body extent -0.87,-0.47 0.87,0.47, height 1
0603S [mil]
  rect 20x35 smd: 1(-30,0) 2(30,0)
  silkscreen extent -10,-17 10,17, body extent -34,-19 34,19, height 39
0805_HV [mil] "0805 with 30mil clearance between pads"
  rect 50x63 smd: 1(-40,0) 2(40,0)
  silkscreen extent -74,-40 74,40, body extent -43,-29 43,29, height 57
0805L [mm] "0805 from SM-752 data"
  rect 1.1x1.4 smd: 1(-0.75,0) 2(0.75,0)
  body extent -1.1,-0.72 1.1,0.72, height 1.45
1206 [mm] "1206 from SM-752 data"
  rect 1.3x1.85 smd: 1(-1.45,0) 2(1.45,0)
  silkscreen extent -2.4,-1.21 2.4,1.21, body extent -1.7,-0.9 1.7,0.9, height 1.35
1206_190 [mm] "1206_190"
  rect 1.1x1.6 smd: 1(-1.7,0) 2(1.7,0)
  silkscreen extent -0.9,-1 0.9,1, body extent -1.75,-0.95 1.75,0.95, height 1.9
Amphenol_12401610E4_2A [mm] "Receptacle, 0.5mm, USB TYPE C, R/A, SMT"
  rect 0.3x0.7 smd: A1(-2.75,0.66) A2(-2.25,0.66) A3(-1.75,0.66) A4(-1.25,0.66) A5(-0.75,0.66) A6(-0.25,0.66) A7(0.25,0.66) A8(0.75,0.66) A9(1.25,0.66) A10(1.75,0.66) A11(2.25,0.66) A12(2.75,0.66) B1(2.5,-1.04) B2(2,-1.04) B3(1.5,-1.04) B4(1,-1.04) B5(0.5,-1.04) B6(0,-1.04) B7(-0.5,-1.04) B8(-1,-1.04) B9(-1.5,-1.04) B10(-2,-1.04) B11(-2.5,-1.04) B12(-3,-1.04)
  round 0 hole 0.65 unplated: ALIGN1(-3.6,0)
  round 0 hole 0.65 slot 0.95 at 0 deg unplated: ALIGN2(3.6,0)
  oval 0.8x1.4 hole 0.5 slot 1.1 at 90 deg: S1(-4.13,-1.25) S2(4.13,-1.25) S3(-4.49,-7.2) S4(4.49,-7.2)
  silkscreen extent -4.6,-9.59 4.6,1.2, body extent -4.59,-9.59 4.59,0.91, height 3.3
AssemblyNote [mm] "Assembly Note"
AssemblyNoteLabel [mm] "Assembly Note for PCB Labels"
CSD17308Q3 [mm] "SMD, 8-Leads, Body 3.3x3.3mm, Pitch 0.65mm"
  rrect45% 0.75x0.44 smd paste-0.05 mask-0.05: 1(-1.525,0.975) 2(-1.525,0.325) 3(-1.525,-0.325) 4(-1.525,-0.975) 5(1.525,-0.975) 6(1.525,-0.325) 7(1.525,0.325) 8(1.525,0.975)
  rrect15% 0.676x1.125 on Top Paste: 9(-0.212,-0.663) 9(-0.212,0.662) 9(0.664,-0.663) 9(0.664,0.662)
  rrect6% 1.775x2.45 on Top Solder: 9(0.327,0)
  rrect8% 2.5x2.55 smd paste-1.5 mask-1.5: 9(0.65,0)
  rrect29% 0.5x0.34 on Top Solder: 9(1.175,-0.975) 9(1.175,-0.325) 9(1.175,0.325) 9(1.175,0.975)
  silkscreen extent -1.8,-1.8 1.8,1.8, body extent -1.65,-1.65 1.65,1.65, height 1.1
DBV0006A_N [mm] "SOT23, 6-Leads, Body 2.9x1.6mm, Pitch 0.95mm, Lead Span 2.8mm, IPC Medium Density"
  rrect17% 1x0.6 smd: 1(-1.375,0.95) 2(-1.375,0) 3(-1.375,-0.95) 4(1.375,-0.95) 5(1.375,0) 6(1.375,0.95)
  silkscreen extent -1.68,-1.55 0.5,1.55, body extent -1.42,-1.46 1.42,1.46, height 1.12
DQG0008A [mm] "SMD, 8-Leads, Body 3.3x3.3mm, Pitch 0.65mm"
  rrect45% 0.75x0.44 smd paste-0.05 mask-0.05: 1(-1.525,0.975) 2(-1.525,0.325) 3(-1.525,-0.325) 4(-1.525,-0.975) 5(1.525,-0.975) 6(1.525,-0.325) 7(1.525,0.325) 8(1.525,0.975)
  rrect15% 0.676x1.125 on Top Paste: 9(-0.212,0.662) 9(-0.212,-0.663) 9(0.664,0.662) 9(0.664,-0.663)
  rrect6% 1.775x2.45 on Top Solder: 9(0.327,0)
  rrect8% 2.5x2.55 smd paste-1.5 mask-1.5: 9(0.65,0)
  rrect29% 0.5x0.34 on Top Solder: 9(1.175,0.975) 9(1.175,-0.325) 9(1.175,0.325) 9(1.175,-0.975)
  silkscreen extent -1.8,-1.8 1.8,1.8, body extent -1.65,-1.65 1.65,1.65, height 1.1
DRL0006A [mm] "SOTFL, 6-Flat Leads, Body 1.2x1.6x0.6mm, Pitch 0.5mm, TI recommended"
  rect 0.5x0.3 smd: 1(-0.75,0.5) 2(-0.75,0) 3(-0.75,-0.5) 4(0.75,-0.5) 5(0.75,0) 6(0.75,0.5)
  silkscreen extent -0.9,-0.95 0.9,0.95, body extent -0.85,-0.85 0.85,0.85, height 0.62
DRV0006A [mm] "SON, 6-Leads, Body 2x2mm, Pitch 0.65mm, Thermal Pad 1.6x1mm, TI Recommended"
  rrect33% 0.45x0.3 smd: 1(-0.975,0.65) 2(-0.975,0) 3(-0.975,-0.65) 4(0.975,-0.65) 5(0.975,0) 6(0.975,0.65)
  rrect14% 1x0.7 on Top Paste: 7(0,-0.45) 7(0,0.45)
  rrect10% 1x1.6 smd paste-0.5: 7(0,0)
  silkscreen extent -1.05,-1.2 1.05,1.2, body extent -1.05,-1.05 1.05,1.05, height 0.81
FCI_20021121-00014x4 [mm] "Header, 1.27mm, 7x2, SMT"
  rect 2.4x0.76 smd: 1(-1.95,3.81) 2(1.95,3.81) 3(-1.95,2.54) 4(1.95,2.54) 5(-1.95,1.27) 6(1.95,1.27) 7(-1.95,0) 8(1.95,0) 9(-1.95,-1.27) 10(1.95,-1.27) 11(-1.95,-2.54) 12(1.95,-2.54) 13(-1.95,-3.81) 14(1.95,-3.81)
  silkscreen extent -2.12,-4.44 0.5,4.86, body extent -2.75,-4.45 2.75,4.44, height 4.5
Harwin_M22-5330405 [mm] "Header, 2mm, 4x1, R/A, SMT"
  rect 0.89x2.03 smd: 1(-3,0) 2(-1,0) 3(1,0) 4(3,0)
  silkscreen extent -4.5,-3.93 4,-2.17, body extent -4,-8.36 4,0.64, height 2
LED_LTST-C190 [mm] "Lite-On"
  rect 0.8x0.8 smd: 1(-0.75,0) 2(0.75,0)
  silkscreen extent -1.1,-0.8 1.8,0.8, body extent -0.85,-0.45 0.85,0.45, height 0.9
Net-Tie_10mil [mil] "10mil net tie, no solder mask opening, no solder paste"
  rect 10x10 smd paste-5 mask-5: 1(-10,0) 2(10,0)
  Top Layer region: -6,5 6,5 6,-5 -6,-5
Pb-Free_Overlay_Small [mm]
  silkscreen extent -1.17,-1.17 1.17,1.16
PowerPAK_1212-8 [mm] "Vishay PowerPAK 1212-8, Body 3.4x3.2mm (max), Pitch 0.65mm, IPC Medium Density"
  rrect50% 0.73x0.4 smd paste-0.05 mask-0.05: 1(-1.535,0.991) 2(-1.535,0.33) 3(-1.535,-0.33) 4(-1.535,-0.991)
  rrect50% 0.71x0.4 smd paste-0.05 mask-0.05: 5(1.545,-0.991) 6(1.545,-0.33) 7(1.545,0.33) 8(1.545,0.991)
  rrect30% 0.33x0.6 on Bottom Paste: 9(-0.195,-1.55) 9(-0.195,1.55)
  rrect30% 0.33x3.7 on Bottom Solder: 9(-0.195,0)
  rrect11% 1.3x0.94 on Bottom Paste: 9(0.39,-0.57) 9(0.39,0.57)
  rrect6% 1.6x2.28 on Bottom Solder: 9(0.54,0)
  rrect9% 2.31x3.3 smd paste-2 mask-2: 9(0.745,0)
  Top Layer region: -0.41,-1.8 -0.41,1.8 -0.402,1.838 -0.381,1.871 -0.348,1.892 -0.31,1.9 -0.31,1.9 -0.08,1.9 -0.042,1.892 -0.009,1.871 0.012,1.838 0.02,1.8 0.02,1.8 0.02,-1.8 0.012,-1.838 -0.009,-1.871 -0.042,-1.892 -0.08,-1.9 -0.08,-1.9 -0.31,-1.9 -0.348,-1.892 -0.381,-1.871 -0.402,-1.838 -0.41,-1.8
  silkscreen extent -1.75,-1.75 1.75,1.75, body extent -1.65,-1.66 1.65,1.64, height 1.08
PW0024A_N [mm] "TSOP, 24-Leads, Body 7.8x4.4mm, Pitch 0.65mm, IPC Medium Density"
  oval 1.4x0.45 smd: 1(-2.95,3.575) 2(-2.95,2.925) 3(-2.95,2.275) 4(-2.95,1.625) 5(-2.95,0.975) 6(-2.95,0.325) 7(-2.95,-0.325) 8(-2.95,-0.975) 9(-2.95,-1.625) 10(-2.95,-2.275) 11(-2.95,-2.925) 12(-2.95,-3.575) 13(2.95,-3.575) 14(2.95,-2.925) 15(2.95,-2.275) 16(2.95,-1.625) 17(2.95,-0.975) 18(2.95,-0.325) 19(2.95,0.325) 20(2.95,0.975) 21(2.95,1.625) 22(2.95,2.275) 23(2.95,2.925) 24(2.95,3.575)
  silkscreen extent -3.51,-3.95 1.6,4.04, body extent -3.21,-3.9 3.21,3.9, height 1
RGT0016C [mm] "QFN, 16-Leads, Body 3x3mm, Pitch 0.5mm, Thermal Pad 1.7x1.7mm, TI Recommended"
  rrect40% 0.6x0.25 smd: 1(-1.4,0.75) 2(-1.4,0.25) 3(-1.4,-0.25) 4(-1.4,-0.75) 9(1.4,-0.75) 10(1.4,-0.25) 11(1.4,0.25) 12(1.4,0.75)
  rrect40% 0.25x0.6 smd: 5(-0.75,-1.4) 6(-0.25,-1.4) 7(0.25,-1.4) 8(0.75,-1.4) 13(0.75,1.4) 14(0.25,1.4) 15(-0.25,1.4) 16(-0.75,1.4)
  rrect6% 1.55x1.55 on Top Paste: 17(0,0)
  rrect6% 1.7x1.7 smd paste-0.85: 17(0,0)
  silkscreen extent -1.72,-1.73 1.72,1.73, body extent -1.57,-1.57 1.58,1.58, height 1.01
RHA0040B [mm] "QFN, 40-Leads, Body 6x6mm, Pitch 0.5mm, Thermal Pad 4.15 x 4.15mm, TI Recommended"
  rrect45% 0.6x0.22 smd mask+0.07: 1(-2.9,2.25) 2(-2.9,1.75) 3(-2.9,1.25) 4(-2.9,0.75) 5(-2.9,0.25) 6(-2.9,-0.25) 7(-2.9,-0.75) 8(-2.9,-1.25) 9(-2.9,-1.75) 10(-2.9,-2.25) 21(2.9,-2.25) 22(2.9,-1.75) 23(2.9,-1.25) 24(2.9,-0.75) 25(2.9,-0.25) 26(2.9,0.25) 27(2.9,0.75) 28(2.9,1.25) 29(2.9,1.75) 30(2.9,2.25)
  rrect45% 0.22x0.6 smd mask+0.07: 11(-2.25,-2.9) 12(-1.75,-2.9) 13(-1.25,-2.9) 14(-0.75,-2.9) 15(-0.25,-2.9) 16(0.25,-2.9) 17(0.75,-2.9) 18(1.25,-2.9) 19(1.75,-2.9) 20(2.25,-2.9) 31(2.25,2.9) 32(1.75,2.9) 33(1.25,2.9) 34(0.75,2.9) 35(0.25,2.9) 36(-0.25,2.9) 37(-0.75,2.9) 38(-1.25,2.9) 39(-1.75,2.9) 40(-2.25,2.9)
  rrect9% 1.17x1.17 on Top Paste: 41(-1.37,1.37) 41(-1.37,0) 41(-1.37,-1.37) 41(0,1.37) 41(0,0) 41(0,-1.37) 41(1.37,1.37) 41(1.37,0) 41(1.37,-1.37)
  rrect2% 4.15x4.15 smd paste-2.1: 41(0,0)
  silkscreen extent -3.22,-3.22 3.22,3.22, body extent -3,-3 3,3, height 1
RSN0032B [mm] "Texas Instruments"
  rrect50% 0.55x0.2 smd: 1(-1.925,1.4) 2(-1.925,1) 3(-1.925,0.6) 4(-1.925,0.2) 5(-1.925,-0.2) 6(-1.925,-0.6) 7(-1.925,-1) 8(-1.925,-1.4) 17(1.925,-1.4) 18(1.925,-1) 19(1.925,-0.6) 20(1.925,-0.2) 21(1.925,0.2) 22(1.925,0.6) 23(1.925,1) 24(1.925,1.4)
  rrect50% 0.2x0.55 smd: 9(-1.4,-1.925) 10(-1,-1.925) 11(-0.6,-1.925) 12(-0.2,-1.925) 13(0.2,-1.925) 14(0.6,-1.925) 15(1,-1.925) 16(1.4,-1.925) 25(1.4,1.925) 26(1,1.925) 27(0.6,1.925) 28(0.2,1.925) 29(-0.2,1.925) 30(-0.6,1.925) 31(-1,1.925) 32(-1.4,1.925)
  rrect8% 1.23x1.23 on Top Paste: 33(-0.715,0.715) 33(-0.715,-0.715) 33(0.715,0.715) 33(0.715,-0.715)
  rrect4% 2.8x2.8 smd paste-1.4: 33(0,0)
  body extent -2.05,-2.05 2.05,2.05, height 0.8
RUK0020B [mm]
  rrect50% 0.6x0.2 smd: 1(-1.4,0.8) 2(-1.4,0.4) 3(-1.4,0) 4(-1.4,-0.4) 5(-1.4,-0.8) 11(1.4,-0.8) 12(1.4,-0.4) 13(1.4,0) 14(1.4,0.4) 15(1.4,0.8)
  rrect50% 0.2x0.6 smd: 6(-0.8,-1.4) 7(-0.4,-1.4) 8(0,-1.4) 9(0.4,-1.4) 10(0.8,-1.4) 16(0.8,1.4) 17(0.4,1.4) 18(0,1.4) 19(-0.4,1.4) 20(-0.8,1.4)
  rrect13% 0.75x0.75 on Top Paste: 21(-0.475,0.475) 21(-0.475,-0.475) 21(0.475,0.475) 21(0.475,-0.475)
  rrect6% 1.7x1.7 smd paste-0.85: 21(0,0)
  silkscreen extent -1.68,-1.68 1.68,1.68, body extent -1.5,-1.5 1.5,1.5, height 0.8
Samtec_FLE-107-01-x-DV [mm] "Receptacle, 1.27mm, 7x2, SMT"
  rect 0.74x1.675 smd: 1(-3.81,1.843) 2(-3.81,-1.843) 3(-2.54,1.843) 4(-2.54,-1.843) 5(-1.27,1.843) 6(-1.27,-1.843) 7(0,1.843) 8(0,-1.843) 9(1.27,1.843) 10(1.27,-1.843) 11(2.54,1.843) 12(2.54,-1.843) 13(3.81,1.843) 14(3.81,-1.843)
  silkscreen extent -4.8,-1.66 4.5,1.66, body extent -4.5,-2.3 4.5,2.3, height 4.55
SM_RADIAL_6.3AMM [mm] "Nichicon 6.3x5.8"
  rect 3.5x1.6 smd: 1(-2.7,0) 2(2.7,0)
  silkscreen extent -3.3,-3.29 3.3,3.31, body extent -3.5,-3.3 3.5,3.3, height 6.11
SOD-323 [mm] "NXP recommended land pattern"
  rect 0.6x0.6 smd paste-0.05: 1(-1.1,0) 2(1.1,0)
  silkscreen extent -2.06,-0.86 1.53,0.86, body extent -1.3,-0.67 1.3,0.68, height 1.1
SOD-523 [mm] "NXP Semiconductor recommended land pattern, nominal STEP model"
  rect 0.8x0.6 smd paste-0.05: 1(-0.55,0) 2(0.55,0)
  silkscreen extent -1.65,-0.66 1.2,0.66, body extent -0.8,-0.4 0.8,0.4, height 0.72
SOT-23 [mm] "SOT23, 3-Leads, Body 2.9x1.3mm, Pitch 0.95mm, Lead Span 2.5mm, IPC Medium Density"
  rrect50% 1x0.6 smd: 1(-1.2,0.95) 2(-1.2,-0.95) 3(1.2,0)
  silkscreen extent -1.62,-1.5 0.7,1.5, body extent -1.16,-1.45 1.21,1.45, height 1
SOT-323 [mm] "Diodes Inc recommended land pattern.  2016-02-24"
  rrect21% 0.6x0.47 smd: 1(-0.95,0.65) 2(-0.95,-0.65) 3(0.95,0)
  silkscreen extent -1.14,-1.22 0.77,1.22, body extent -1.13,-1.13 1.12,1.12, height 1.13
SW_B3U-1100P [mm] "SMD, 3-Leads, Body 3x2.5mm"
  rect 0.8x1.8 smd: 1(-1.7,0) 2(1.7,0)
  rect 0.8x1.2 smd: 3(0,1.65)
  silkscreen extent -2.83,-1.25 1.5,1.25, body extent -2,-1.25 2,1.9, height 1.6
WURTH_614104150121 [mm] "USB2.0 A, TH"
  rect 1.6x1.6 hole 0.94: 1(3.5,0)
  round 1.6 hole 0.94: 2(1,0) 3(-1,0) 4(-3.5,0)
  oval 1.3x2.2 hole 0.6 slot 1.5 at 90 deg: 5(-6.4,-7.35) 6(6.4,-7.35)
  silkscreen extent -7.3,-9.9 7.3,0.72, body extent -7.3,-9.9 7.3,0.1, height 6.93
XEL6060 [mm] "SMD, 2-Leads, Body 6.36x6.56mm"
  rrect7% 1.43x5.5 smd: 1(-2.02,0) 2(2.02,0)
  silkscreen extent -3.28,-3.38 3.28,3.38, body extent -3.28,-3.38 3.28,3.38, height 6.1
XFL4020 [mm] "Coilcraft XFL4020 7/18/12"
  rect 0.98x3.4 smd: 1(-1.181,0) 2(1.181,0)
  silkscreen extent -2.16,-2.16 2.16,2.16, body extent -2.15,-2.15 2.15,2.15, height 2.1
YFP0009-C01 [mm] "DSBGA, 9-Balls, Body 1.38x1.335mm, Pitch 0.4mm"
  round 0.23 smd paste-0.13 mask+0.038: A1(-0.4,0.4) A2(0,0.4) A3(0.4,0.4) B1(-0.4,0) B2(0,0) B3(0.4,0) C1(-0.4,-0.4) C2(0,-0.4) C3(0.4,-0.4)
  body extent -0.7,-0.68 0.7,0.68, height 0.5

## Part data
C1 C96 C97 C98 C99: "CAP, CERM, 1 µF, 16 V,+/- 10%, X5R, 0402", Cap_Case=0402, Manufacturer=TDK, Supplier Part Number 1=445-4978-1-ND, TempCo=X5R, Tolerance_%=10, Value2=16V, ValueDisplayed=1µF
C2 C152 C153: "CAP, CERM, 100 pF, 50 V, +/- 5%, C0G/NP0, 0402", Cap_Case=0402, Manufacturer=MuRata, Supplier Part Number 1=81-GRM1555C1H101JA1D, TempCo=C0G/NP0, Tolerance_%=5, Value1=Unknown, Value2=50V, ValueDisplayed=100pF
C3 C4 C5 C30 C102 C104 C105 C107: "CAP, CERM, 0.1 µF, 16 V, +/- 10%, X5R, 0402", Cap_Case=0402, Manufacturer=MuRata, Supplier Part Number 1=490-5415-1-ND, TempCo=X5R, Tolerance_%=10, Value1=Unknown, Value2=16V, ValueDisplayed=0.1µF
C6 C8: "CAP, CERM, 47 µF, 6.3 V, +/- 20%, X5R, 0805", Cap_Case=0805, Manufacturer="Taiyo Yuden", Supplier Part Number 1=587-1779-1-ND, TempCo=X5R, Tolerance_%=20, Value1=Unknown, Value2=6.3V, ValueDisplayed=47µF
C7 C22: "CAP, CERM, 1 µF, 10 V,+/- 20%, X5R, 0402", Cap_Case=0402, Manufacturer="Wurth Elektronik", Supplier Part Number 1=732-7489-1-ND, TempCo=X5R, Tolerance_%=20, Value2=10V, ValueDisplayed=1µF
C9 C123 C126: "CAP, CERM, 10 µF, 25 V, +/- 20%, X5R, 0603", Cap_Case=0603, Manufacturer=MuRata, Supplier Part Number 1=490-7202-1-ND, TempCo=X5R, Tolerance_%=20, Value1=Unknown, Value2=25V, ValueDisplayed=10µF
C10 C119 C124: "CAP, CERM, 0.1 µF, 25 V, +/- 10%, X5R, 0402", Cap_Case=0402, Manufacturer=MuRata, Supplier Part Number 1=490-5920-1-ND, TempCo=X5R, Tolerance_%=10, Value1=Unknown, Value2=25V, ValueDisplayed=0.1µF
C11 C12: "CAP, CERM, 0.033 µF, 50 V, +/- 10%, X7R, 0603", Cap_Case=0603, Manufacturer=MuRata, Supplier Part Number 1=490-3286-1-ND, TempCo=X7R, Tolerance_%=10, Value1=Unknown, Value2=50V, ValueDisplayed=0.033µF
C13: "CAP, CERM, 0.47 µF, 50 V, +/- 10%, X7R, 0805", Cap_Case=0805, Manufacturer=MuRata, Supplier Part Number 1=490-3328-1-ND, TempCo=X7R, Tolerance_%=10, Value1=Unknown, Value2=50V, ValueDisplayed=0.47µF
C14 C138 C139: "CAP, CERM, 0.047 µF, 16 V, +/- 10%, X5R, 0402", Cap_Case=0402, Manufacturer=MuRata, Supplier Part Number 1=GRM155R61C473KA01D-ND, TempCo=X5R, Tolerance_%=10, Value1=Unknown, Value2=16V, ValueDisplayed=0.047µF
C15 C145: library part CMP-0006234-2, "CAP, CERM, 1000 pF, 25 V, +/- 5%, X7R, 0402", Cap_Case=0402, Manufacturer=Kemet, Supplier Part Number 1=399-7752-1-ND, TempCo=X7R, Tolerance_%=5%, Value1=Unknown, Value2=25V, ValueDisplayed=1000pF
C16: "CAP, CERM, 10 µF, 10 V,+/- 20%, X5R, 0402", Cap_Case=0402, Manufacturer="Samsung Electro-Mechanics", Supplier Part Number 1=1276-1450-1-ND, TempCo=X5R, Tolerance_%=20, Value2=10V, ValueDisplayed=10µF
C17 C116 C127 C128: "CAP, CERM, 10 µF, 35 V, +/- 10%, X5R, 0805", Cap_Case=0805, Manufacturer=MuRata, Supplier Part Number 1=490-10514-1-ND, TempCo=X5R, Tolerance_%=10, Value1=Unknown, Value2=35V, ValueDisplayed=10µF
C18 C19: "CAP, CERM, 220 pF, 50 V,+/- 5%, C0G/NP0, 0402", Cap_Case=0402, Manufacturer=MuRata, Supplier Part Number 1=490-1293-1-ND, TempCo=C0G/NP0, Tolerance_%=5, Value2=50V, ValueDisplayed=220pF
C20: "CAP, CERM, 4.7 µF, 6.3 V, +/- 20%, X5R, 0402", Cap_Case=0402, Manufacturer=TDK, Supplier Part Number 1=445-7395-1-ND, TempCo=X5R, Tolerance_%=20, Value1=Unknown, Value2=6.3V, ValueDisplayed=4.7µF
C21: "CAP, CERM, 1 µF, 35 V, +/- 10%, X5R, 0402", Cap_Case=0402, Manufacturer=MuRata, Supplier Part Number 1=490-10019-1-ND, TempCo=X5R, Tolerance_%=10, Value1=Unknown, Value2=35V, ValueDisplayed=1µF
C23: "CAP, CERM, 0.1 µF, 50 V, +/- 20%, X5R, 0402", Cap_Case=0402, Manufacturer=MuRata, Supplier Part Number 1=GRM155R61H104ME14D-ND, TempCo=X5R, Tolerance_%=20, Value1=Unknown, Value2=50V, ValueDisplayed=0.1µF
C24 C27 C28 C33 C108: "CAP, CERM, 0.01 µF, 16 V,+/- 10%, X5R, 0402", Cap_Case=0402, Manufacturer=MuRata, Supplier Part Number 1=GRM155R61C103KA01D-ND, TempCo=X5R, Tolerance_%=10, Value2=16V, ValueDisplayed=0.01µF
C25 C26: "CAP, CERM, 0.1 µF, 10 V, +/- 10%, X5R, 0402", Cap_Case=0402, Manufacturer=TDK, Supplier Part Number 1=445-1265-1-ND, TempCo=X5R, Tolerance_%=10, Value1=Unknown, Value2=10V, ValueDisplayed=0.1µF
C29 C31: "CAP, CERM, 47 pF, 50 V, +/- 1%, C0G/NP0, 0402", Cap_Case=0402, Manufacturer=MuRata, Supplier Part Number 1=490-6241-1-ND, TempCo=C0G/NP0, Tolerance_%=1, Value1=Unknown, Value2=50V, ValueDisplayed=47pF
C32: "CAP, CERM, 1100 pF, 50 V, +/- 5%, C0G/NP0, 0402", Cap_Case=0402, Manufacturer=Kemet, Supplier Part Number 1=399-9948-1-ND, TempCo=C0G/NP0, Tolerance_%=5, Value1=Unknown, Value2=50V, ValueDisplayed=1100pF
C103: "CAP, CERM, 1 µF, 25 V, +/- 10%, X5R, 0402", Cap_Case=0402, Manufacturer=TDK, Supplier Part Number 1=445-9066-1-ND, TempCo=X5R, Tolerance_%=10, Value1=Unknown, Value2=25V, ValueDisplayed=1µF
C106: "CAP, CERM, 3300 pF, 50 V, +/- 10%, X7R, 0402", Cap_Case=0402, Manufacturer=MuRata, Supplier Part Number 1=490-3248-1-ND, TempCo=X7R, Tolerance_%=10, Value1=Unknown, Value2=50V, ValueDisplayed=3300pF
C114: "CAP, CERM, 0.01 µF, 50 V, +/- 10%, X7R, 0402", Cap_Case=0402, Manufacturer=MuRata, Supplier Part Number 1=490-4516-1-ND, TempCo=X7R, Tolerance_%=10, Value1=Unknown, Value2=50V, ValueDisplayed=0.01µF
